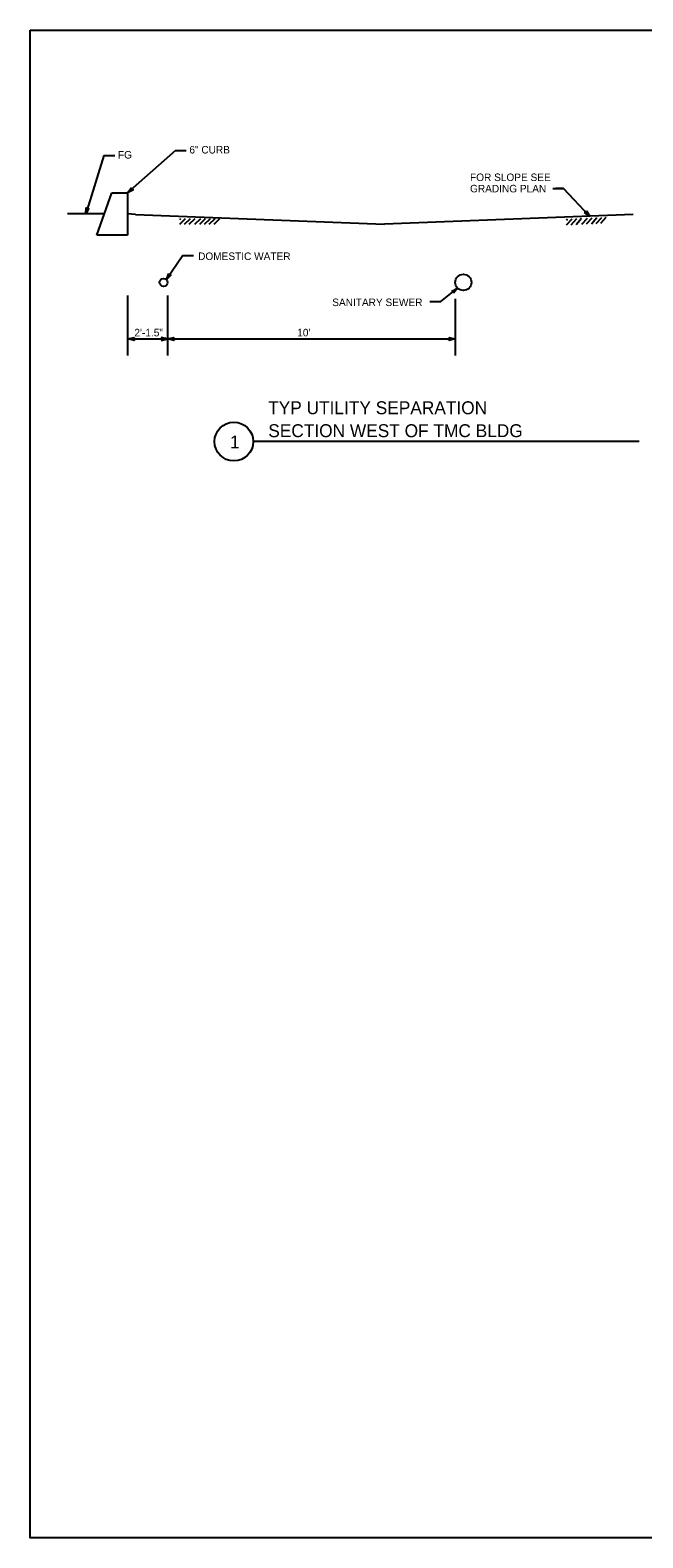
# Model space of a CAD drawing. Extents: x -1680 to 1155, y -802 to 799.
# Drawn here: x -549 to 20, y -802 to 598 of the extents above; entities that cross this region are included whole.
import ezdxf

# ---------------------------------------------------------------- set-up
doc = ezdxf.new("R2010")
doc.units = 0
for name, color, linetype in [('Default', 7, 'Continuous'), ('G-TTLB-VIEW', 7, 'Continuous'), ('Nongeo Data(60)', 7, 'Continuous')]:
    doc.layers.add(name, color=color, linetype=linetype)

msp = doc.modelspace()

# ---------------------------------------------------------------- linework, layer by layer
at = {"layer": 'Default'}
for p, q in [((-480.3, 481.6), (-497, 427.4)), ((-413.9, 486.3), (-458.3, 447)), ((-458.3, 447), (-458.3, 407.8)), ((-479.9, 427.4), (-514.1, 427.4)), ((-451, 426.7), (-458.3, 427.4)), ((-458.3, 407.8), (-487, 407.8))]:
    msp.add_line(p, q, dxfattribs=at)
msp.add_circle((-425, 363.8), 3.75, dxfattribs=at)
at = {"layer": 'G-TTLB-VIEW'}
msp.add_lwpolyline([(-548.8, 598), (1053.5, 598), (1053.5, -802), (-548.8, -802)], close=True, dxfattribs=at)
at = {"layer": 'Nongeo Data(60)'}
for p, q in [((-480.3, 481.6), (-470.3, 481.6)), ((-413.9, 486.3), (-403.9, 486.3)), ((-458.3, 447), (-454.6, 451.9)), ((-452.9, 449.9), (-458.3, 447)), ((-457.3, 447.9), (-454.6, 451.5)), ((-453.3, 450), (-457.3, 447.9)), ((-456.2, 448.8), (-454.5, 451.1)), ((-453.7, 450.2), (-456.2, 448.8)), ((-455.2, 449.7), (-454.4, 450.7)), ((-454.1, 450.3), (-455.2, 449.7)), ((-454.6, 451.9), (-454.6, 451.9)), ((-454.6, 451.9), (-454.4, 450.4)), ((-454.4, 450.4), (-452.9, 449.9)), ((-452.9, 449.9), (-452.9, 449.9)), ((-63.6, 450.9), (-53.6, 450.9)), ((-53.6, 450.9), (-61, 450.9)), ((-29.3, 425.1), (-53.6, 450.9)), ((-487, 407.8), (-472.9, 447)), ((-472.9, 447), (-458.3, 447)), ((-458.3, 447), (-458.3, 447)), ((-497, 427.4), (-496.8, 433.5)), ((-494.2, 432.8), (-497, 427.4)), ((-497, 427.4), (-497, 427.4)), ((-496.8, 433.5), (-496.8, 433.5)), ((-496.8, 433.5), (-495.7, 432.4)), ((-496.7, 428.7), (-496.5, 433.2)), ((-494.6, 432.7), (-496.7, 428.7)), ((-496.3, 430.1), (-496.2, 432.9)), ((-495, 432.6), (-496.3, 430.1)), ((-496, 431.4), (-495.9, 432.6)), ((-495.4, 432.5), (-496, 431.4)), ((-495.7, 432.4), (-494.2, 432.8)), ((-494.2, 432.8), (-494.2, 432.8)), ((-451, 426.7), (-220, 417.8)), ((-409.9, 417.8), (-404.5, 423.2)), ((-409.9, 422.3), (-408.9, 423.2)), ((-405.5, 417.8), (-400.1, 423.2)), ((-401.1, 417.8), (-395.6, 423.2)), ((-395.8, 417.8), (-390.4, 423.2)), ((-391.4, 417.8), (-385.9, 423.2)), ((-387, 417.8), (-381.5, 423.2)), ((-382.6, 417.8), (-377.1, 423.2)), ((-378.1, 417.8), (-372.8, 423.1)), ((11, 426.7), (-220, 417.8)), ((-51, 421.7), (-50.1, 422.7)), ((-50.9, 417.2), (-45.7, 422.9)), ((-46.5, 417.4), (-41.3, 423.1)), ((-42.1, 417.6), (-36.9, 423.3)), ((-36.8, 417.9), (-31.6, 423.6)), ((-34.4, 428.6), (-32.9, 428.9)), ((-29.3, 425.1), (-34.4, 428.6)), ((-34.4, 428.6), (-34.4, 428.6)), ((-30.2, 426.2), (-34, 428.7)), ((-31.2, 427.2), (-33.6, 428.8)), ((-32.1, 428.2), (-33.2, 428.8)), ((-32.9, 428.9), (-32.4, 430.4)), ((-32.8, 429.2), (-32.1, 428.2)), ((-32.6, 429.6), (-31.2, 427.2)), ((-32.5, 430), (-30.2, 426.1)), ((-32.4, 430.4), (-32.4, 430.4)), ((-32.4, 430.4), (-29.3, 425.1)), ((-32.4, 418.1), (-27.2, 423.8)), ((-29.3, 425.1), (-29.3, 425.1)), ((-27.9, 418.3), (-22.7, 424)), ((-23.5, 418.5), (-18.3, 424.2)), ((-19.1, 418.7), (-14.1, 424.3)), ((-407.1, 388.9), (-422.3, 366.5)), ((-407.1, 388.9), (-397.1, 388.9)), ((-422.3, 366.5), (-420.1, 372.2)), ((-417.8, 370.7), (-422.3, 366.5)), ((-422.3, 366.5), (-422.3, 366.5)), ((-421.5, 367.6), (-419.9, 371.8)), ((-418.3, 370.7), (-421.5, 367.6)), ((-420.8, 368.7), (-419.7, 371.4)), ((-418.7, 370.7), (-420.8, 368.7)), ((-420.1, 372.2), (-420.1, 372.2)), ((-420.1, 372.2), (-419.4, 370.8)), ((-420, 369.9), (-419.5, 371)), ((-419.1, 370.7), (-420, 369.9)), ((-419.4, 370.8), (-417.8, 370.7)), ((-417.8, 370.7), (-417.8, 370.7)), ((-458.3, 351.6), (-458.3, 295.8)), ((-421.2, 351.6), (-421.2, 295.8)), ((-167.7, 346.1), (-152, 358.5)), ((-157.5, 355.8), (-152, 358.5)), ((-156.1, 355.2), (-157.5, 355.8)), ((-157.5, 355.8), (-157.5, 355.8)), ((-157.1, 355.7), (-153.1, 357.6)), ((-156.7, 355.5), (-154.2, 356.8)), ((-156.4, 355.4), (-155.2, 355.9)), ((-155.9, 353.7), (-156.1, 355.2)), ((-154.2, 356.8), (-156, 354.5)), ((-155.2, 355.9), (-156, 354.9)), ((-152, 358.5), (-155.9, 353.7)), ((-153.1, 357.6), (-155.9, 354.1)), ((-155.9, 353.7), (-155.9, 353.7)), ((-152, 358.5), (-152, 358.5)), ((-177.7, 346.1), (-167.7, 346.1)), ((-154.2, 348.6), (-154.2, 295.8)), ((-458, 311.3), (-452, 312.6)), ((-458, 311.3), (-421.2, 311.3)), ((-452, 309.9), (-458, 311.3)), ((-458, 311.3), (-458, 311.3)), ((-456.6, 311.3), (-452.2, 312.2)), ((-452.2, 310.3), (-456.6, 311.3)), ((-455.2, 311.3), (-452.4, 311.9)), ((-452.4, 310.7), (-455.2, 311.3)), ((-453.8, 311.3), (-452.6, 311.5)), ((-452.6, 311), (-453.8, 311.3)), ((-452, 312.6), (-452.8, 311.3)), ((-452.8, 311.3), (-452, 309.9)), ((-452, 312.6), (-452, 312.6)), ((-452, 309.9), (-452, 309.9)), ((-421.2, 311.3), (-427.2, 312.6)), ((-427.2, 312.6), (-427.2, 312.6)), ((-427.2, 312.6), (-426.4, 311.3)), ((-426.4, 311.3), (-427.2, 309.9)), ((-427.2, 309.9), (-421.2, 311.3)), ((-427.2, 309.9), (-427.2, 309.9)), ((-422.6, 311.3), (-427, 312.2)), ((-427, 310.3), (-422.6, 311.3)), ((-424, 311.3), (-426.8, 311.9)), ((-426.8, 310.7), (-424, 311.3)), ((-425.4, 311.3), (-426.6, 311.5)), ((-426.6, 311), (-425.4, 311.3)), ((-421.2, 311.3), (-415.2, 312.6)), ((-415.2, 309.9), (-421.2, 311.3)), ((-421.2, 311.3), (-421.2, 311.3)), ((-421.2, 311.3), (-154.2, 311.3)), ((-421.2, 311.3), (-421.2, 311.3)), ((-419.8, 311.3), (-415.5, 312.2)), ((-415.4, 310.3), (-419.8, 311.3)), ((-418.5, 311.3), (-415.6, 311.9)), ((-415.7, 310.7), (-418.5, 311.3)), ((-417.1, 311.3), (-415.9, 311.5)), ((-415.8, 311), (-417.1, 311.3)), ((-415.2, 312.6), (-416, 311.3)), ((-416, 311.3), (-415.2, 309.9)), ((-415.2, 312.6), (-415.2, 312.6)), ((-415.2, 309.9), (-415.2, 309.9)), ((-159.4, 311.3), (-160.2, 312.6)), ((-160.2, 312.6), (-160.2, 312.6)), ((-160.2, 312.6), (-154.2, 311.3)), ((-154.2, 311.3), (-160.2, 309.9)), ((-160.2, 309.9), (-159.4, 311.3)), ((-160.2, 309.9), (-160.2, 309.9)), ((-160, 312.3), (-155.6, 311.3)), ((-155.6, 311.3), (-160, 310.3)), ((-159.8, 311.9), (-157, 311.3)), ((-157, 311.3), (-159.8, 310.7)), ((-159.6, 311.6), (-158.4, 311.3)), ((-158.4, 311.3), (-159.6, 311)), ((-154.2, 311.3), (-154.2, 311.3)), ((16.6, 216), (-341.7, 216))]:
    msp.add_line(p, q, dxfattribs=at)
for centre, radius in [((-146.7, 363.8), 7.5), ((-359.7, 216), 18)]:
    msp.add_circle(centre, radius, dxfattribs=at)

# ---------------------------------------------------------------- texts
for s, height, p in [('6" CURB', 7, (-401, 483.5)), ('FG', 7, (-467.3, 478.8)), ('FOR SLOPE SEE', 7, (-140.5, 457.9)), ('GRADING PLAN', 7, (-140.5, 447.4)), ('DOMESTIC WATER', 7, (-392.9, 384.6)), ('SANITARY SEWER', 7, (-268.4, 341.8)), ('2\'-1.5"', 7, (-452, 313.7)), ("10'", 7, (-300.9, 313.7)), ('TYP UTILITY SEPARATION', 12, (-327.9, 241.4)), ('SECTION WEST OF TMC BLDG', 12, (-327.8, 220.1)), ('1', 12, (-363.3, 209.6))]:
    msp.add_text(s, height=height, dxfattribs=at).set_placement(p)

doc.saveas('drawing.dxf')
